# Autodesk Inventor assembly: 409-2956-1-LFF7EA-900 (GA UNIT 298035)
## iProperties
Created: 2010-09
Part Number: 409-2956-1-LFF7EA-900 (GA UNIT 298035)
Document SubType Name: Assembly
Designer: S. Boerckel
Mass: 2.71449e+06 g
Surface Area: 794951 cm^2
Volume: 404621 cm^3
Density: 6.70872 g/cm^3
Description: GENERAL ARRANGEMENT UNIT 298034
Material: ASSEMBLY
SMR: =<MATERIAL>
Author: S. Boerckel
Revision Number: 0
Title: GENERAL ARRANGEMENT UNIT-298034
